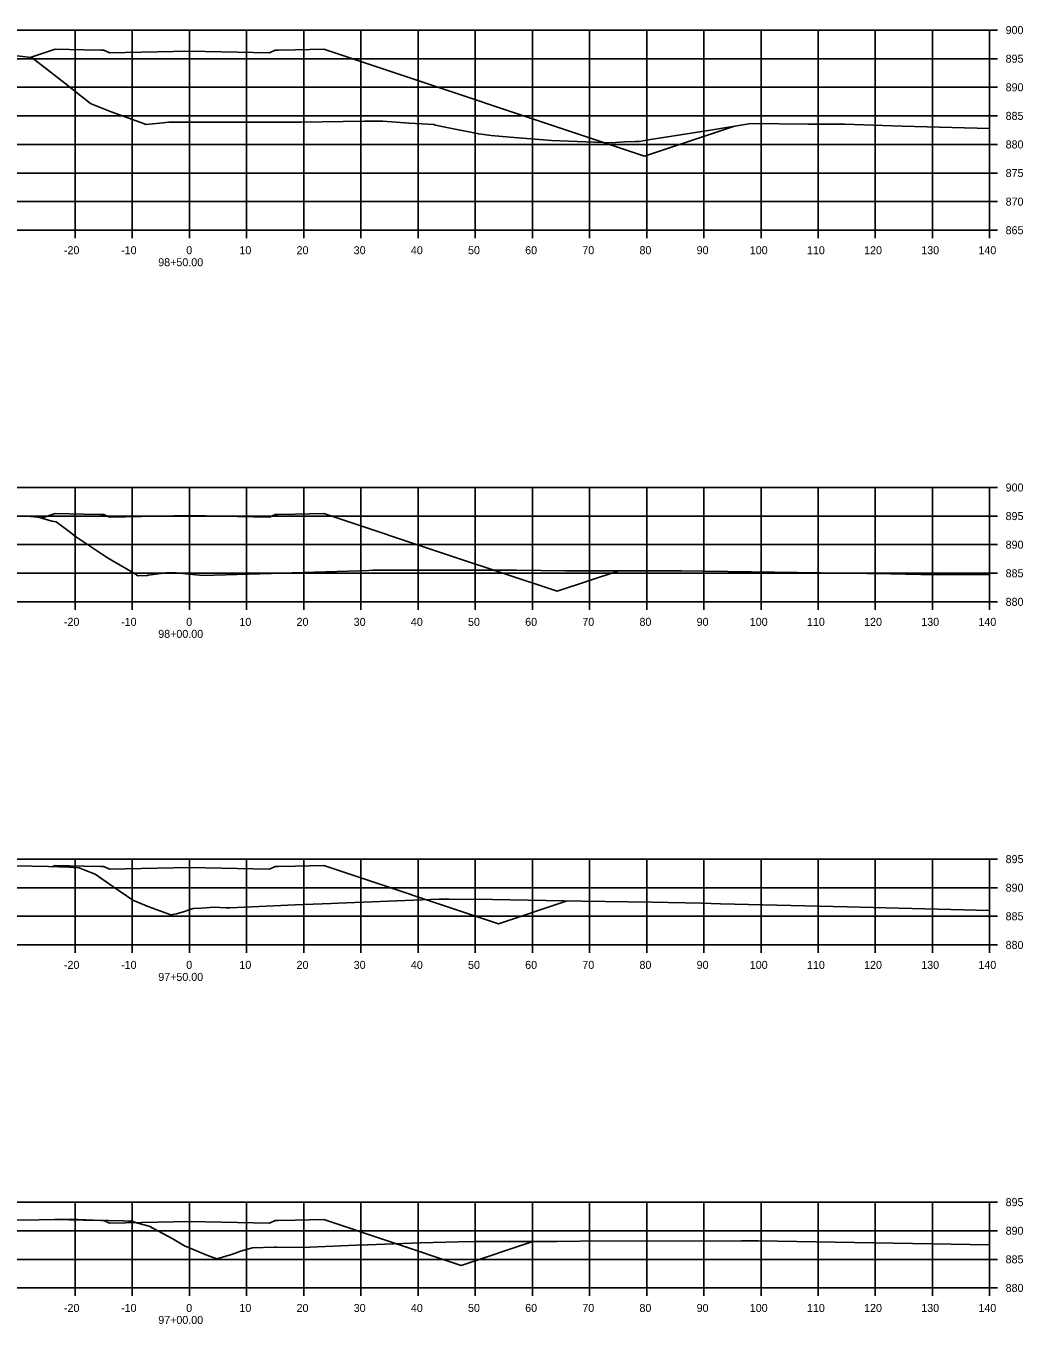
# Model space of a CAD drawing. Extents: x 1098669 to 1198896, y 698679 to 704410.
# Drawn here: x 1113470.3 to 1113644.7, y 701727.2 to 701954.3 of the extents above; entities that cross this region are included whole.
import ezdxf

# ---------------------------------------------------------------- set-up
doc = ezdxf.new("R2010")
doc.units = 0
for name, color, linetype in [('R_Alt Surface', 7, 'Continuous'), ('R_Axis', 7, 'Continuous'), ('R_Axis Annot', 7, 'Continuous'), ('R_Fin Surface', 7, 'Continuous'), ('R_Grid', 7, 'Continuous')]:
    doc.layers.add(name, color=color, linetype=linetype)

msp = doc.modelspace()

# ---------------------------------------------------------------- linework, layer by layer
at = {"layer": 'R_Alt Surface'}
for points in [[(1113467.16, 701949.25), (1113471.22, 701948.74), (1113471.33, 701948.72), (1113477.06, 701944.25), (1113481.58, 701940.72), (1113481.67, 701940.68), (1113485.19, 701939.25), (1113491.01, 701937.15), (1113491.24, 701937.06), (1113493.66, 701937.3), (1113495.29, 701937.46), (1113496.61, 701937.47), (1113512.84, 701937.44), (1113518.34, 701937.46), (1113529.48, 701937.64), (1113531.2, 701937.65), (1113532.69, 701937.66), (1113537.39, 701937.3), (1113541.61, 701937.05), (1113541.9, 701936.95), (1113543.88, 701936.53), (1113549.5, 701935.43), (1113551.66, 701935.14), (1113555.01, 701934.84), (1113562.23, 701934.27), (1113572.71, 701933.82), (1113575.07, 701934.04), (1113576.86, 701934.1), (1113577.45, 701934.08), (1113577.61, 701934.09), (1113579.53, 701934.4), (1113590.04, 701936.08), (1113597.09, 701937.21), (1113607.09, 701937.1), (1113613.46, 701937.13), (1113623.59, 701936.73), (1113638.87, 701936.36)], [(1113464.06, 701868.63), (1113471.04, 701868.46), (1113472.26, 701868.36), (1113472.58, 701868.34), (1113474.86, 701867.68), (1113475.55, 701867.53), (1113477.81, 701865.84), (1113478.93, 701865), (1113484.38, 701861.4), (1113485.26, 701860.85), (1113489.36, 701858.43), (1113489.85, 701858.1), (1113491.48, 701858.19), (1113491.65, 701858.2), (1113494.71, 701858.61), (1113496.53, 701858.62), (1113501.19, 701858.14), (1113515.13, 701858.57), (1113516.84, 701858.62), (1113528.64, 701859), (1113530.24, 701859.06), (1113530.95, 701859.1), (1113542.88, 701859.11), (1113544.45, 701859.09), (1113556.1, 701859.09), (1113564.62, 701859.01), (1113574.78, 701858.99), (1113584.95, 701858.99), (1113621.52, 701858.44), (1113629.53, 701858.28), (1113638.87, 701858.35)], [(1113468.57, 701807.4), (1113474.18, 701807.25), (1113477.77, 701807.16), (1113478.51, 701807.1), (1113479.59, 701807.03), (1113480.59, 701806.62), (1113482.4, 701805.94), (1113485.49, 701803.79), (1113488.97, 701801.41), (1113491.75, 701800.23), (1113495.59, 701798.84), (1113496.61, 701799.01), (1113498.02, 701799.39), (1113499.01, 701799.73), (1113499.54, 701799.91), (1113500.98, 701800), (1113503.18, 701800.14), (1113505.27, 701800.06), (1113506, 701800.02), (1113517.38, 701800.55), (1113523.68, 701800.8), (1113524.91, 701800.85), (1113542.48, 701801.57), (1113544.3, 701801.57), (1113551.88, 701801.48), (1113567.52, 701801.21), (1113579.74, 701801.01), (1113588.53, 701800.84), (1113591.77, 701800.73), (1113613.97, 701800.19), (1113638.87, 701799.56)], [(1113467.68, 701745.41), (1113472.5, 701745.48), (1113478.01, 701745.56), (1113482.03, 701745.44), (1113487.31, 701745.29), (1113488.16, 701745.24), (1113488.77, 701745.21), (1113489.63, 701744.93), (1113491.82, 701744.37), (1113495.85, 701742.22), (1113498.02, 701740.92), (1113501.91, 701739.3), (1113503.67, 701738.62), (1113506.21, 701739.43), (1113506.95, 701739.65), (1113507.81, 701739.96), (1113509.88, 701740.56), (1113513.72, 701740.68), (1113513.77, 701740.68), (1113514.12, 701740.68), (1113518.61, 701740.65), (1113528.06, 701741.02), (1113530.05, 701741.1), (1113539.28, 701741.46), (1113545.97, 701741.65), (1113548.73, 701741.7), (1113563.17, 701741.66), (1113567.15, 701741.74), (1113595.48, 701741.79), (1113595.74, 701741.8), (1113598.35, 701741.77), (1113638.87, 701741.1)]]:
    msp.add_lwpolyline(points, dxfattribs=at)
at = {"layer": 'R_Axis'}
for p, q in [((1113638.87, 701918.56), (1113638.87, 701953.56)), ((1113640.27, 701953.56), (1113638.87, 701953.56)), ((1113640.27, 701948.56), (1113638.87, 701948.56)), ((1113640.27, 701943.56), (1113638.87, 701943.56)), ((1113640.27, 701938.56), (1113638.87, 701938.56)), ((1113640.27, 701933.56), (1113638.87, 701933.56)), ((1113640.27, 701928.56), (1113638.87, 701928.56)), ((1113640.27, 701923.56), (1113638.87, 701923.56)), ((1113358.87, 701918.56), (1113638.87, 701918.56)), ((1113478.87, 701917.16), (1113478.87, 701918.56)), ((1113488.87, 701917.16), (1113488.87, 701918.56)), ((1113498.87, 701917.16), (1113498.87, 701918.56)), ((1113508.87, 701917.16), (1113508.87, 701918.56)), ((1113518.87, 701917.16), (1113518.87, 701918.56)), ((1113528.87, 701917.16), (1113528.87, 701918.56)), ((1113538.87, 701917.16), (1113538.87, 701918.56)), ((1113548.87, 701917.16), (1113548.87, 701918.56)), ((1113558.87, 701917.16), (1113558.87, 701918.56)), ((1113568.87, 701917.16), (1113568.87, 701918.56)), ((1113578.87, 701917.16), (1113578.87, 701918.56)), ((1113588.87, 701917.16), (1113588.87, 701918.56)), ((1113598.87, 701917.16), (1113598.87, 701918.56)), ((1113608.87, 701917.16), (1113608.87, 701918.56)), ((1113618.87, 701917.16), (1113618.87, 701918.56)), ((1113628.87, 701917.16), (1113628.87, 701918.56)), ((1113638.87, 701917.16), (1113638.87, 701918.56)), ((1113640.27, 701918.56), (1113638.87, 701918.56)), ((1113638.87, 701853.56), (1113638.87, 701873.56)), ((1113640.27, 701873.56), (1113638.87, 701873.56)), ((1113640.27, 701868.56), (1113638.87, 701868.56)), ((1113640.27, 701863.56), (1113638.87, 701863.56)), ((1113640.27, 701858.56), (1113638.87, 701858.56)), ((1113358.87, 701853.56), (1113638.87, 701853.56)), ((1113478.87, 701852.16), (1113478.87, 701853.56)), ((1113488.87, 701852.16), (1113488.87, 701853.56)), ((1113498.87, 701852.16), (1113498.87, 701853.56)), ((1113508.87, 701852.16), (1113508.87, 701853.56)), ((1113518.87, 701852.16), (1113518.87, 701853.56)), ((1113528.87, 701852.16), (1113528.87, 701853.56)), ((1113538.87, 701852.16), (1113538.87, 701853.56)), ((1113548.87, 701852.16), (1113548.87, 701853.56)), ((1113558.87, 701852.16), (1113558.87, 701853.56)), ((1113568.87, 701852.16), (1113568.87, 701853.56)), ((1113578.87, 701852.16), (1113578.87, 701853.56)), ((1113588.87, 701852.16), (1113588.87, 701853.56)), ((1113598.87, 701852.16), (1113598.87, 701853.56)), ((1113608.87, 701852.16), (1113608.87, 701853.56)), ((1113618.87, 701852.16), (1113618.87, 701853.56)), ((1113628.87, 701852.16), (1113628.87, 701853.56)), ((1113638.87, 701852.16), (1113638.87, 701853.56)), ((1113640.27, 701853.56), (1113638.87, 701853.56)), ((1113638.87, 701793.56), (1113638.87, 701808.56)), ((1113640.27, 701808.56), (1113638.87, 701808.56)), ((1113640.27, 701803.56), (1113638.87, 701803.56)), ((1113640.27, 701798.56), (1113638.87, 701798.56)), ((1113358.87, 701793.56), (1113638.87, 701793.56)), ((1113478.87, 701792.16), (1113478.87, 701793.56)), ((1113488.87, 701792.16), (1113488.87, 701793.56)), ((1113498.87, 701792.16), (1113498.87, 701793.56)), ((1113508.87, 701792.16), (1113508.87, 701793.56)), ((1113518.87, 701792.16), (1113518.87, 701793.56)), ((1113528.87, 701792.16), (1113528.87, 701793.56)), ((1113538.87, 701792.16), (1113538.87, 701793.56)), ((1113548.87, 701792.16), (1113548.87, 701793.56)), ((1113558.87, 701792.16), (1113558.87, 701793.56)), ((1113568.87, 701792.16), (1113568.87, 701793.56)), ((1113578.87, 701792.16), (1113578.87, 701793.56)), ((1113588.87, 701792.16), (1113588.87, 701793.56)), ((1113598.87, 701792.16), (1113598.87, 701793.56)), ((1113608.87, 701792.16), (1113608.87, 701793.56)), ((1113618.87, 701792.16), (1113618.87, 701793.56)), ((1113628.87, 701792.16), (1113628.87, 701793.56)), ((1113638.87, 701792.16), (1113638.87, 701793.56)), ((1113640.27, 701793.56), (1113638.87, 701793.56)), ((1113638.87, 701733.56), (1113638.87, 701748.56)), ((1113640.27, 701748.56), (1113638.87, 701748.56)), ((1113640.27, 701743.56), (1113638.87, 701743.56)), ((1113640.27, 701738.56), (1113638.87, 701738.56)), ((1113358.87, 701733.56), (1113638.87, 701733.56)), ((1113478.87, 701732.16), (1113478.87, 701733.56)), ((1113488.87, 701732.16), (1113488.87, 701733.56)), ((1113498.87, 701732.16), (1113498.87, 701733.56)), ((1113508.87, 701732.16), (1113508.87, 701733.56)), ((1113518.87, 701732.16), (1113518.87, 701733.56)), ((1113528.87, 701732.16), (1113528.87, 701733.56)), ((1113538.87, 701732.16), (1113538.87, 701733.56)), ((1113548.87, 701732.16), (1113548.87, 701733.56)), ((1113558.87, 701732.16), (1113558.87, 701733.56)), ((1113568.87, 701732.16), (1113568.87, 701733.56)), ((1113578.87, 701732.16), (1113578.87, 701733.56)), ((1113588.87, 701732.16), (1113588.87, 701733.56)), ((1113598.87, 701732.16), (1113598.87, 701733.56)), ((1113608.87, 701732.16), (1113608.87, 701733.56)), ((1113618.87, 701732.16), (1113618.87, 701733.56)), ((1113628.87, 701732.16), (1113628.87, 701733.56)), ((1113638.87, 701732.16), (1113638.87, 701733.56)), ((1113640.27, 701733.56), (1113638.87, 701733.56))]:
    msp.add_line(p, q, dxfattribs=at)
at = {"layer": 'R_Fin Surface'}
for points in [[(1113470.99, 701948.77), (1113475.37, 701950.23), (1113480.37, 701950.13), (1113483.37, 701950.07), (1113483.87, 701950.07), (1113484.87, 701949.59), (1113498.87, 701949.87), (1113512.87, 701949.59), (1113513.87, 701950.07), (1113514.37, 701950.07), (1113517.37, 701950.13), (1113522.37, 701950.23), (1113578.51, 701931.51), (1113594.23, 701936.75)], [(1113473, 701868.22), (1113475.37, 701869), (1113480.37, 701868.9), (1113483.37, 701868.84), (1113483.87, 701868.84), (1113484.87, 701868.36), (1113498.87, 701868.64), (1113512.87, 701868.36), (1113513.87, 701868.84), (1113514.37, 701868.84), (1113517.37, 701868.9), (1113522.37, 701869), (1113544.7, 701861.56), (1113563.19, 701855.4), (1113573.97, 701858.99)], [(1113474.77, 701807.24), (1113475.37, 701807.44), (1113480.37, 701807.34), (1113483.37, 701807.28), (1113483.87, 701807.28), (1113484.87, 701806.8), (1113498.87, 701807.08), (1113512.87, 701806.8), (1113513.87, 701807.28), (1113514.37, 701807.28), (1113517.37, 701807.34), (1113522.37, 701807.44), (1113552.92, 701797.25), (1113564.93, 701801.26)], [(1113475.36, 701745.53), (1113475.37, 701745.52), (1113480.37, 701745.42), (1113483.37, 701745.36), (1113483.87, 701745.36), (1113484.87, 701744.88), (1113498.87, 701745.16), (1113512.87, 701744.88), (1113513.87, 701745.36), (1113514.37, 701745.36), (1113517.37, 701745.42), (1113522.37, 701745.52), (1113546.42, 701737.5), (1113558.94, 701741.68)]]:
    msp.add_lwpolyline(points, dxfattribs=at)
at = {"layer": 'R_Grid'}
for p, q in [((1113358.87, 701953.56), (1113638.87, 701953.56)), ((1113478.87, 701918.56), (1113478.87, 701953.56)), ((1113488.87, 701918.56), (1113488.87, 701953.56)), ((1113498.87, 701918.56), (1113498.87, 701953.56)), ((1113508.87, 701918.56), (1113508.87, 701953.56)), ((1113518.87, 701918.56), (1113518.87, 701953.56)), ((1113528.87, 701918.56), (1113528.87, 701953.56)), ((1113538.87, 701918.56), (1113538.87, 701953.56)), ((1113548.87, 701918.56), (1113548.87, 701953.56)), ((1113558.87, 701918.56), (1113558.87, 701953.56)), ((1113568.87, 701918.56), (1113568.87, 701953.56)), ((1113578.87, 701918.56), (1113578.87, 701953.56)), ((1113588.87, 701918.56), (1113588.87, 701953.56)), ((1113598.87, 701918.56), (1113598.87, 701953.56)), ((1113608.87, 701918.56), (1113608.87, 701953.56)), ((1113618.87, 701918.56), (1113618.87, 701953.56)), ((1113628.87, 701918.56), (1113628.87, 701953.56)), ((1113638.87, 701918.56), (1113638.87, 701953.56)), ((1113358.87, 701948.56), (1113638.87, 701948.56)), ((1113358.87, 701943.56), (1113638.87, 701943.56)), ((1113358.87, 701938.56), (1113638.87, 701938.56)), ((1113358.87, 701933.56), (1113638.87, 701933.56)), ((1113358.87, 701928.56), (1113638.87, 701928.56)), ((1113358.87, 701923.56), (1113638.87, 701923.56)), ((1113358.87, 701918.56), (1113638.87, 701918.56)), ((1113358.87, 701873.56), (1113638.87, 701873.56)), ((1113478.87, 701853.56), (1113478.87, 701873.56)), ((1113488.87, 701853.56), (1113488.87, 701873.56)), ((1113498.87, 701853.56), (1113498.87, 701873.56)), ((1113508.87, 701853.56), (1113508.87, 701873.56)), ((1113518.87, 701853.56), (1113518.87, 701873.56)), ((1113528.87, 701853.56), (1113528.87, 701873.56)), ((1113538.87, 701853.56), (1113538.87, 701873.56)), ((1113548.87, 701853.56), (1113548.87, 701873.56)), ((1113558.87, 701853.56), (1113558.87, 701873.56)), ((1113568.87, 701853.56), (1113568.87, 701873.56)), ((1113578.87, 701853.56), (1113578.87, 701873.56)), ((1113588.87, 701853.56), (1113588.87, 701873.56)), ((1113598.87, 701853.56), (1113598.87, 701873.56)), ((1113608.87, 701853.56), (1113608.87, 701873.56)), ((1113618.87, 701853.56), (1113618.87, 701873.56)), ((1113628.87, 701853.56), (1113628.87, 701873.56)), ((1113638.87, 701853.56), (1113638.87, 701873.56)), ((1113358.87, 701868.56), (1113638.87, 701868.56)), ((1113358.87, 701863.56), (1113638.87, 701863.56)), ((1113358.87, 701858.56), (1113638.87, 701858.56)), ((1113358.87, 701853.56), (1113638.87, 701853.56)), ((1113358.87, 701808.56), (1113638.87, 701808.56)), ((1113478.87, 701793.56), (1113478.87, 701808.56)), ((1113488.87, 701793.56), (1113488.87, 701808.56)), ((1113498.87, 701793.56), (1113498.87, 701808.56)), ((1113508.87, 701793.56), (1113508.87, 701808.56)), ((1113518.87, 701793.56), (1113518.87, 701808.56)), ((1113528.87, 701793.56), (1113528.87, 701808.56)), ((1113538.87, 701793.56), (1113538.87, 701808.56)), ((1113548.87, 701793.56), (1113548.87, 701808.56)), ((1113558.87, 701793.56), (1113558.87, 701808.56)), ((1113568.87, 701793.56), (1113568.87, 701808.56)), ((1113578.87, 701793.56), (1113578.87, 701808.56)), ((1113588.87, 701793.56), (1113588.87, 701808.56)), ((1113598.87, 701793.56), (1113598.87, 701808.56)), ((1113608.87, 701793.56), (1113608.87, 701808.56)), ((1113618.87, 701793.56), (1113618.87, 701808.56)), ((1113628.87, 701793.56), (1113628.87, 701808.56)), ((1113638.87, 701793.56), (1113638.87, 701808.56)), ((1113358.87, 701803.56), (1113638.87, 701803.56)), ((1113358.87, 701798.56), (1113638.87, 701798.56)), ((1113358.87, 701793.56), (1113638.87, 701793.56)), ((1113358.87, 701748.56), (1113638.87, 701748.56)), ((1113478.87, 701733.56), (1113478.87, 701748.56)), ((1113488.87, 701733.56), (1113488.87, 701748.56)), ((1113498.87, 701733.56), (1113498.87, 701748.56)), ((1113508.87, 701733.56), (1113508.87, 701748.56)), ((1113518.87, 701733.56), (1113518.87, 701748.56)), ((1113528.87, 701733.56), (1113528.87, 701748.56)), ((1113538.87, 701733.56), (1113538.87, 701748.56)), ((1113548.87, 701733.56), (1113548.87, 701748.56)), ((1113558.87, 701733.56), (1113558.87, 701748.56)), ((1113568.87, 701733.56), (1113568.87, 701748.56)), ((1113578.87, 701733.56), (1113578.87, 701748.56)), ((1113588.87, 701733.56), (1113588.87, 701748.56)), ((1113598.87, 701733.56), (1113598.87, 701748.56)), ((1113608.87, 701733.56), (1113608.87, 701748.56)), ((1113618.87, 701733.56), (1113618.87, 701748.56)), ((1113628.87, 701733.56), (1113628.87, 701748.56)), ((1113638.87, 701733.56), (1113638.87, 701748.56)), ((1113358.87, 701743.56), (1113638.87, 701743.56)), ((1113358.87, 701738.56), (1113638.87, 701738.56)), ((1113358.87, 701733.56), (1113638.87, 701733.56))]:
    msp.add_line(p, q, dxfattribs=at)

# ---------------------------------------------------------------- texts
at = {"layer": 'R_Axis Annot'}
for s, p in [('900', (1113641.67, 701952.86)), ('895', (1113641.67, 701947.86)), ('890', (1113641.67, 701942.86)), ('885', (1113641.67, 701937.86)), ('880', (1113641.67, 701932.86)), ('875', (1113641.67, 701927.86)), ('870', (1113641.67, 701922.86)), ('865', (1113641.67, 701917.86)), ('-20', (1113476.91, 701914.36)), ('-10', (1113486.91, 701914.36)), ('0', (1113498.31, 701914.36)), ('10', (1113507.61, 701914.36)), ('20', (1113517.61, 701914.36)), ('30', (1113527.61, 701914.36)), ('40', (1113537.61, 701914.36)), ('50', (1113547.61, 701914.36)), ('60', (1113557.61, 701914.36)), ('70', (1113567.61, 701914.36)), ('80', (1113577.61, 701914.36)), ('90', (1113587.61, 701914.36)), ('100', (1113596.91, 701914.36)), ('110', (1113606.91, 701914.36)), ('120', (1113616.91, 701914.36)), ('130', (1113626.91, 701914.36)), ('140', (1113636.91, 701914.36)), ('98+50.00', (1113493.41, 701912.26)), ('900', (1113641.67, 701872.86)), ('895', (1113641.67, 701867.86)), ('890', (1113641.67, 701862.86)), ('885', (1113641.67, 701857.86)), ('880', (1113641.67, 701852.86)), ('-20', (1113476.91, 701849.36)), ('-10', (1113486.91, 701849.36)), ('0', (1113498.31, 701849.36)), ('10', (1113507.61, 701849.36)), ('20', (1113517.61, 701849.36)), ('30', (1113527.61, 701849.36)), ('40', (1113537.61, 701849.36)), ('50', (1113547.61, 701849.36)), ('60', (1113557.61, 701849.36)), ('70', (1113567.61, 701849.36)), ('80', (1113577.61, 701849.36)), ('90', (1113587.61, 701849.36)), ('100', (1113596.91, 701849.36)), ('110', (1113606.91, 701849.36)), ('120', (1113616.91, 701849.36)), ('130', (1113626.91, 701849.36)), ('140', (1113636.91, 701849.36)), ('98+00.00', (1113493.41, 701847.26)), ('895', (1113641.67, 701807.86)), ('890', (1113641.67, 701802.86)), ('885', (1113641.67, 701797.86)), ('880', (1113641.67, 701792.86)), ('-20', (1113476.91, 701789.36)), ('-10', (1113486.91, 701789.36)), ('0', (1113498.31, 701789.36)), ('10', (1113507.61, 701789.36)), ('20', (1113517.61, 701789.36)), ('30', (1113527.61, 701789.36)), ('40', (1113537.61, 701789.36)), ('50', (1113547.61, 701789.36)), ('60', (1113557.61, 701789.36)), ('70', (1113567.61, 701789.36)), ('80', (1113577.61, 701789.36)), ('90', (1113587.61, 701789.36)), ('100', (1113596.91, 701789.36)), ('110', (1113606.91, 701789.36)), ('120', (1113616.91, 701789.36)), ('130', (1113626.91, 701789.36)), ('140', (1113636.91, 701789.36)), ('97+50.00', (1113493.41, 701787.26)), ('895', (1113641.67, 701747.86)), ('890', (1113641.67, 701742.86)), ('885', (1113641.67, 701737.86)), ('880', (1113641.67, 701732.86)), ('-20', (1113476.91, 701729.36)), ('-10', (1113486.91, 701729.36)), ('0', (1113498.31, 701729.36)), ('10', (1113507.61, 701729.36)), ('20', (1113517.61, 701729.36)), ('30', (1113527.61, 701729.36)), ('40', (1113537.61, 701729.36)), ('50', (1113547.61, 701729.36)), ('60', (1113557.61, 701729.36)), ('70', (1113567.61, 701729.36)), ('80', (1113577.61, 701729.36)), ('90', (1113587.61, 701729.36)), ('100', (1113596.91, 701729.36)), ('110', (1113606.91, 701729.36)), ('120', (1113616.91, 701729.36)), ('130', (1113626.91, 701729.36)), ('140', (1113636.91, 701729.36)), ('97+00.00', (1113493.41, 701727.26))]:
    msp.add_text(s, height=1.4, dxfattribs=at).set_placement(p)

doc.saveas('drawing.dxf')
